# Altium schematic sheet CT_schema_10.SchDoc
size 741 x 377 mm
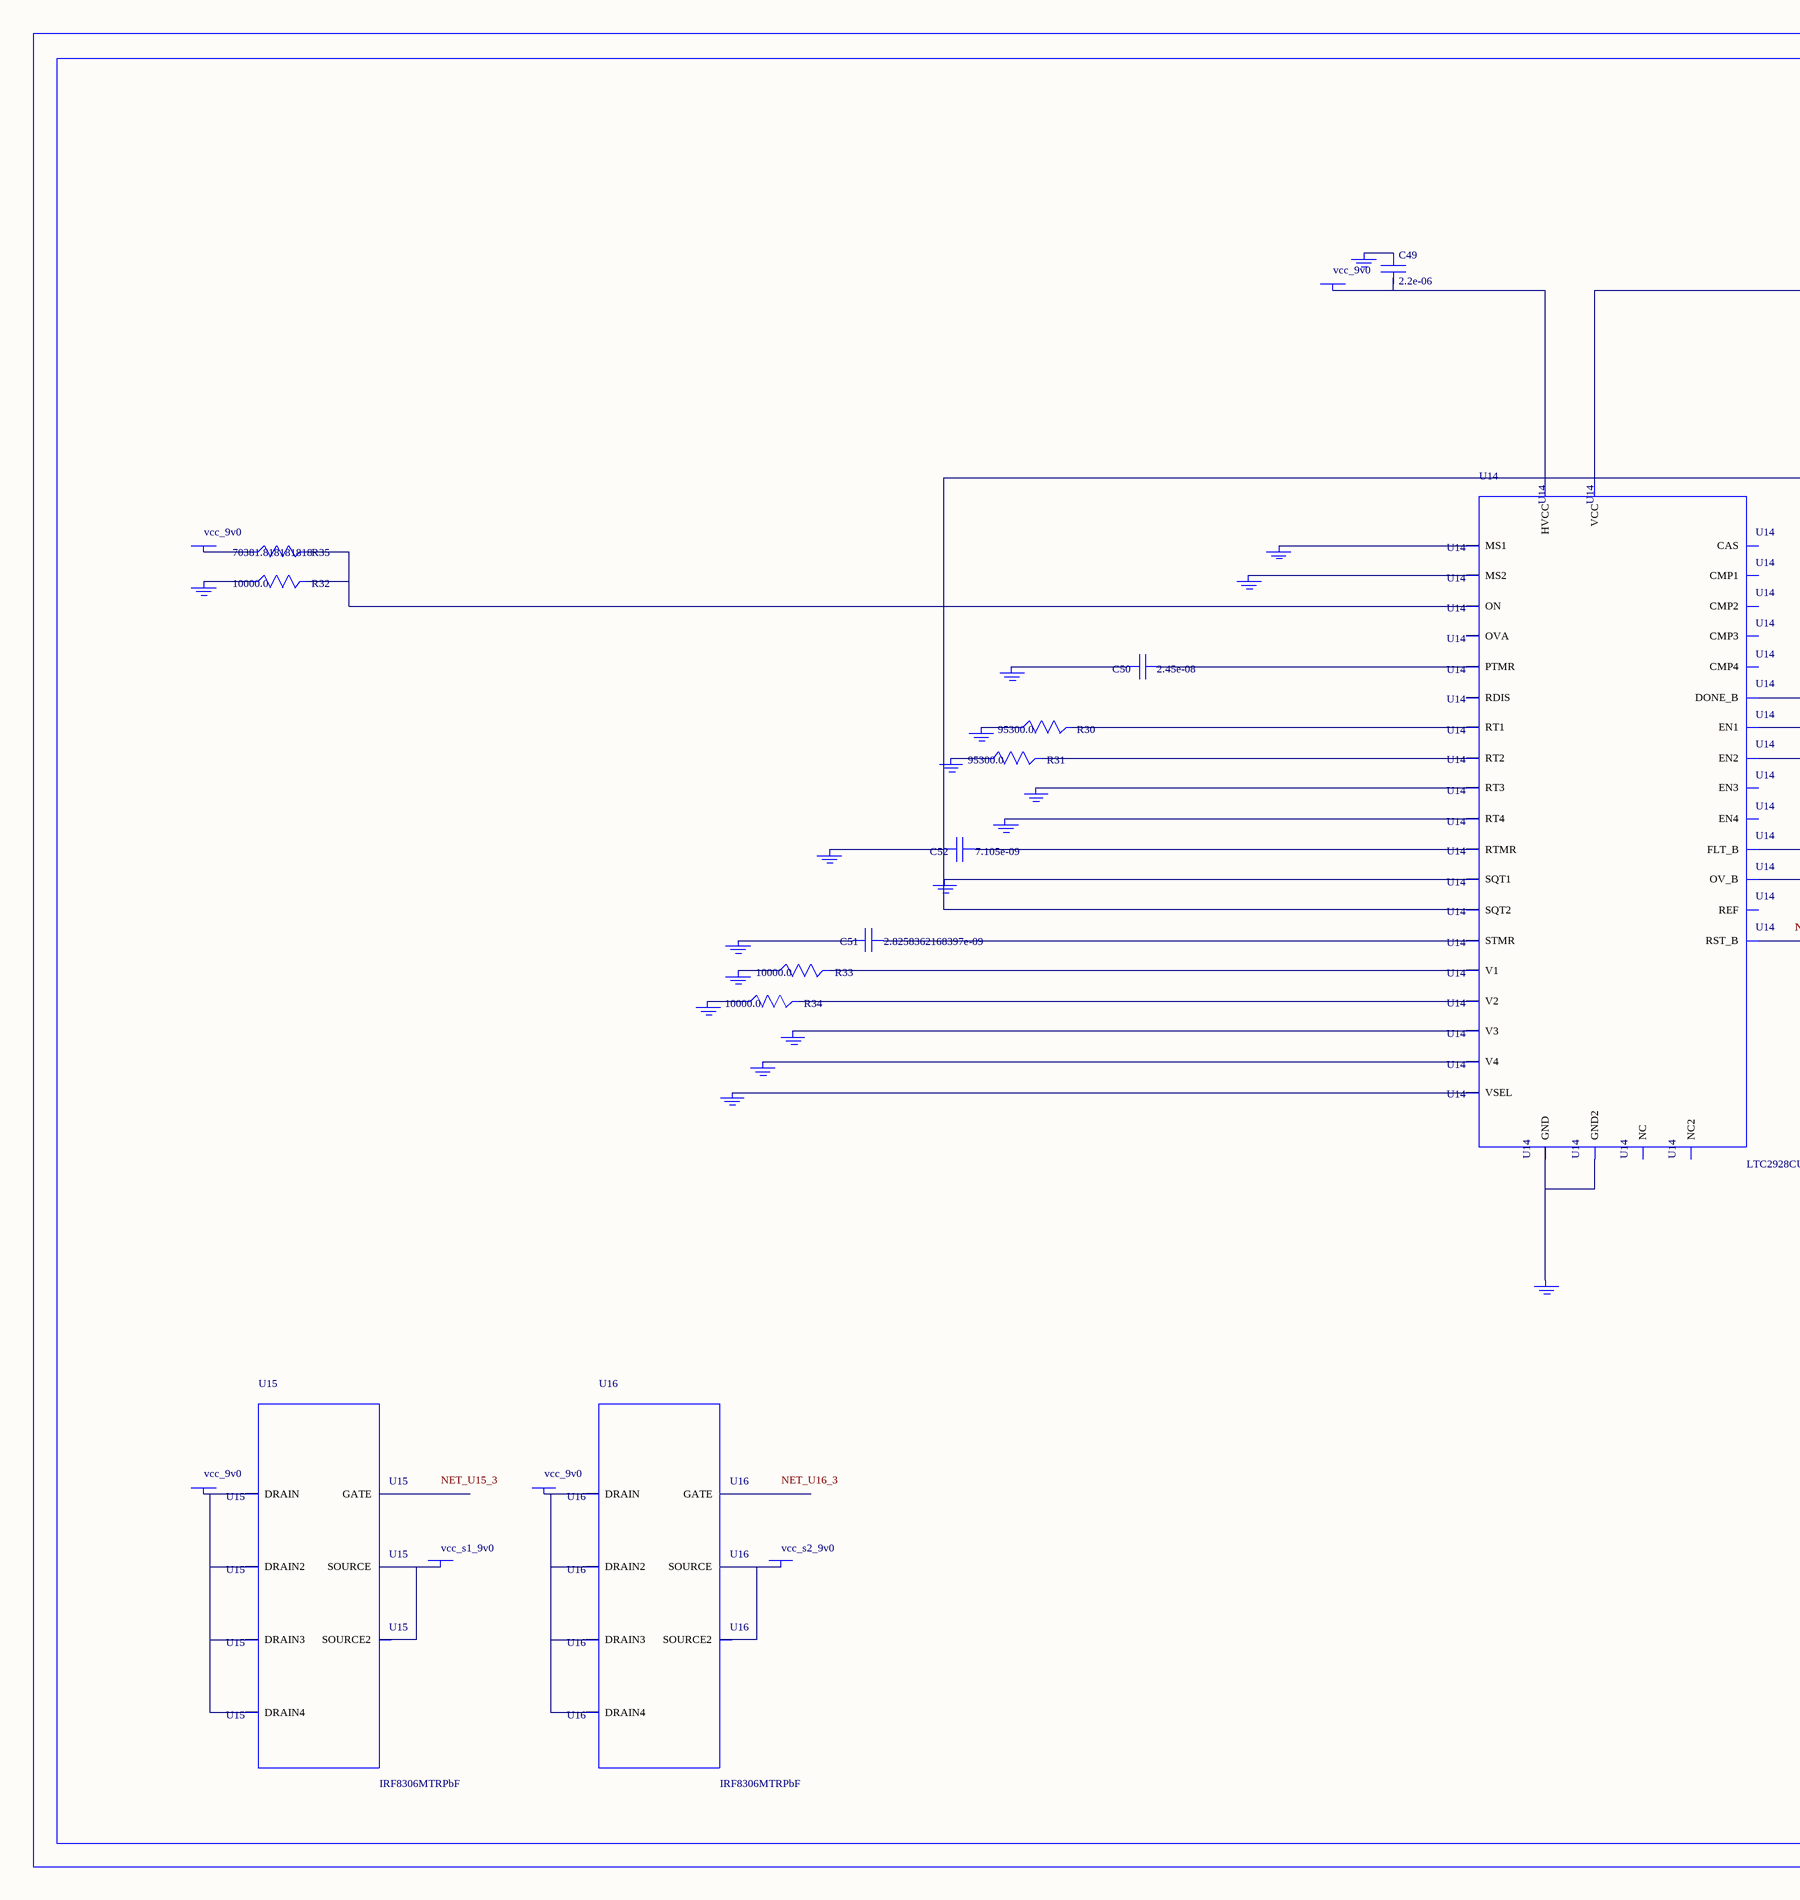
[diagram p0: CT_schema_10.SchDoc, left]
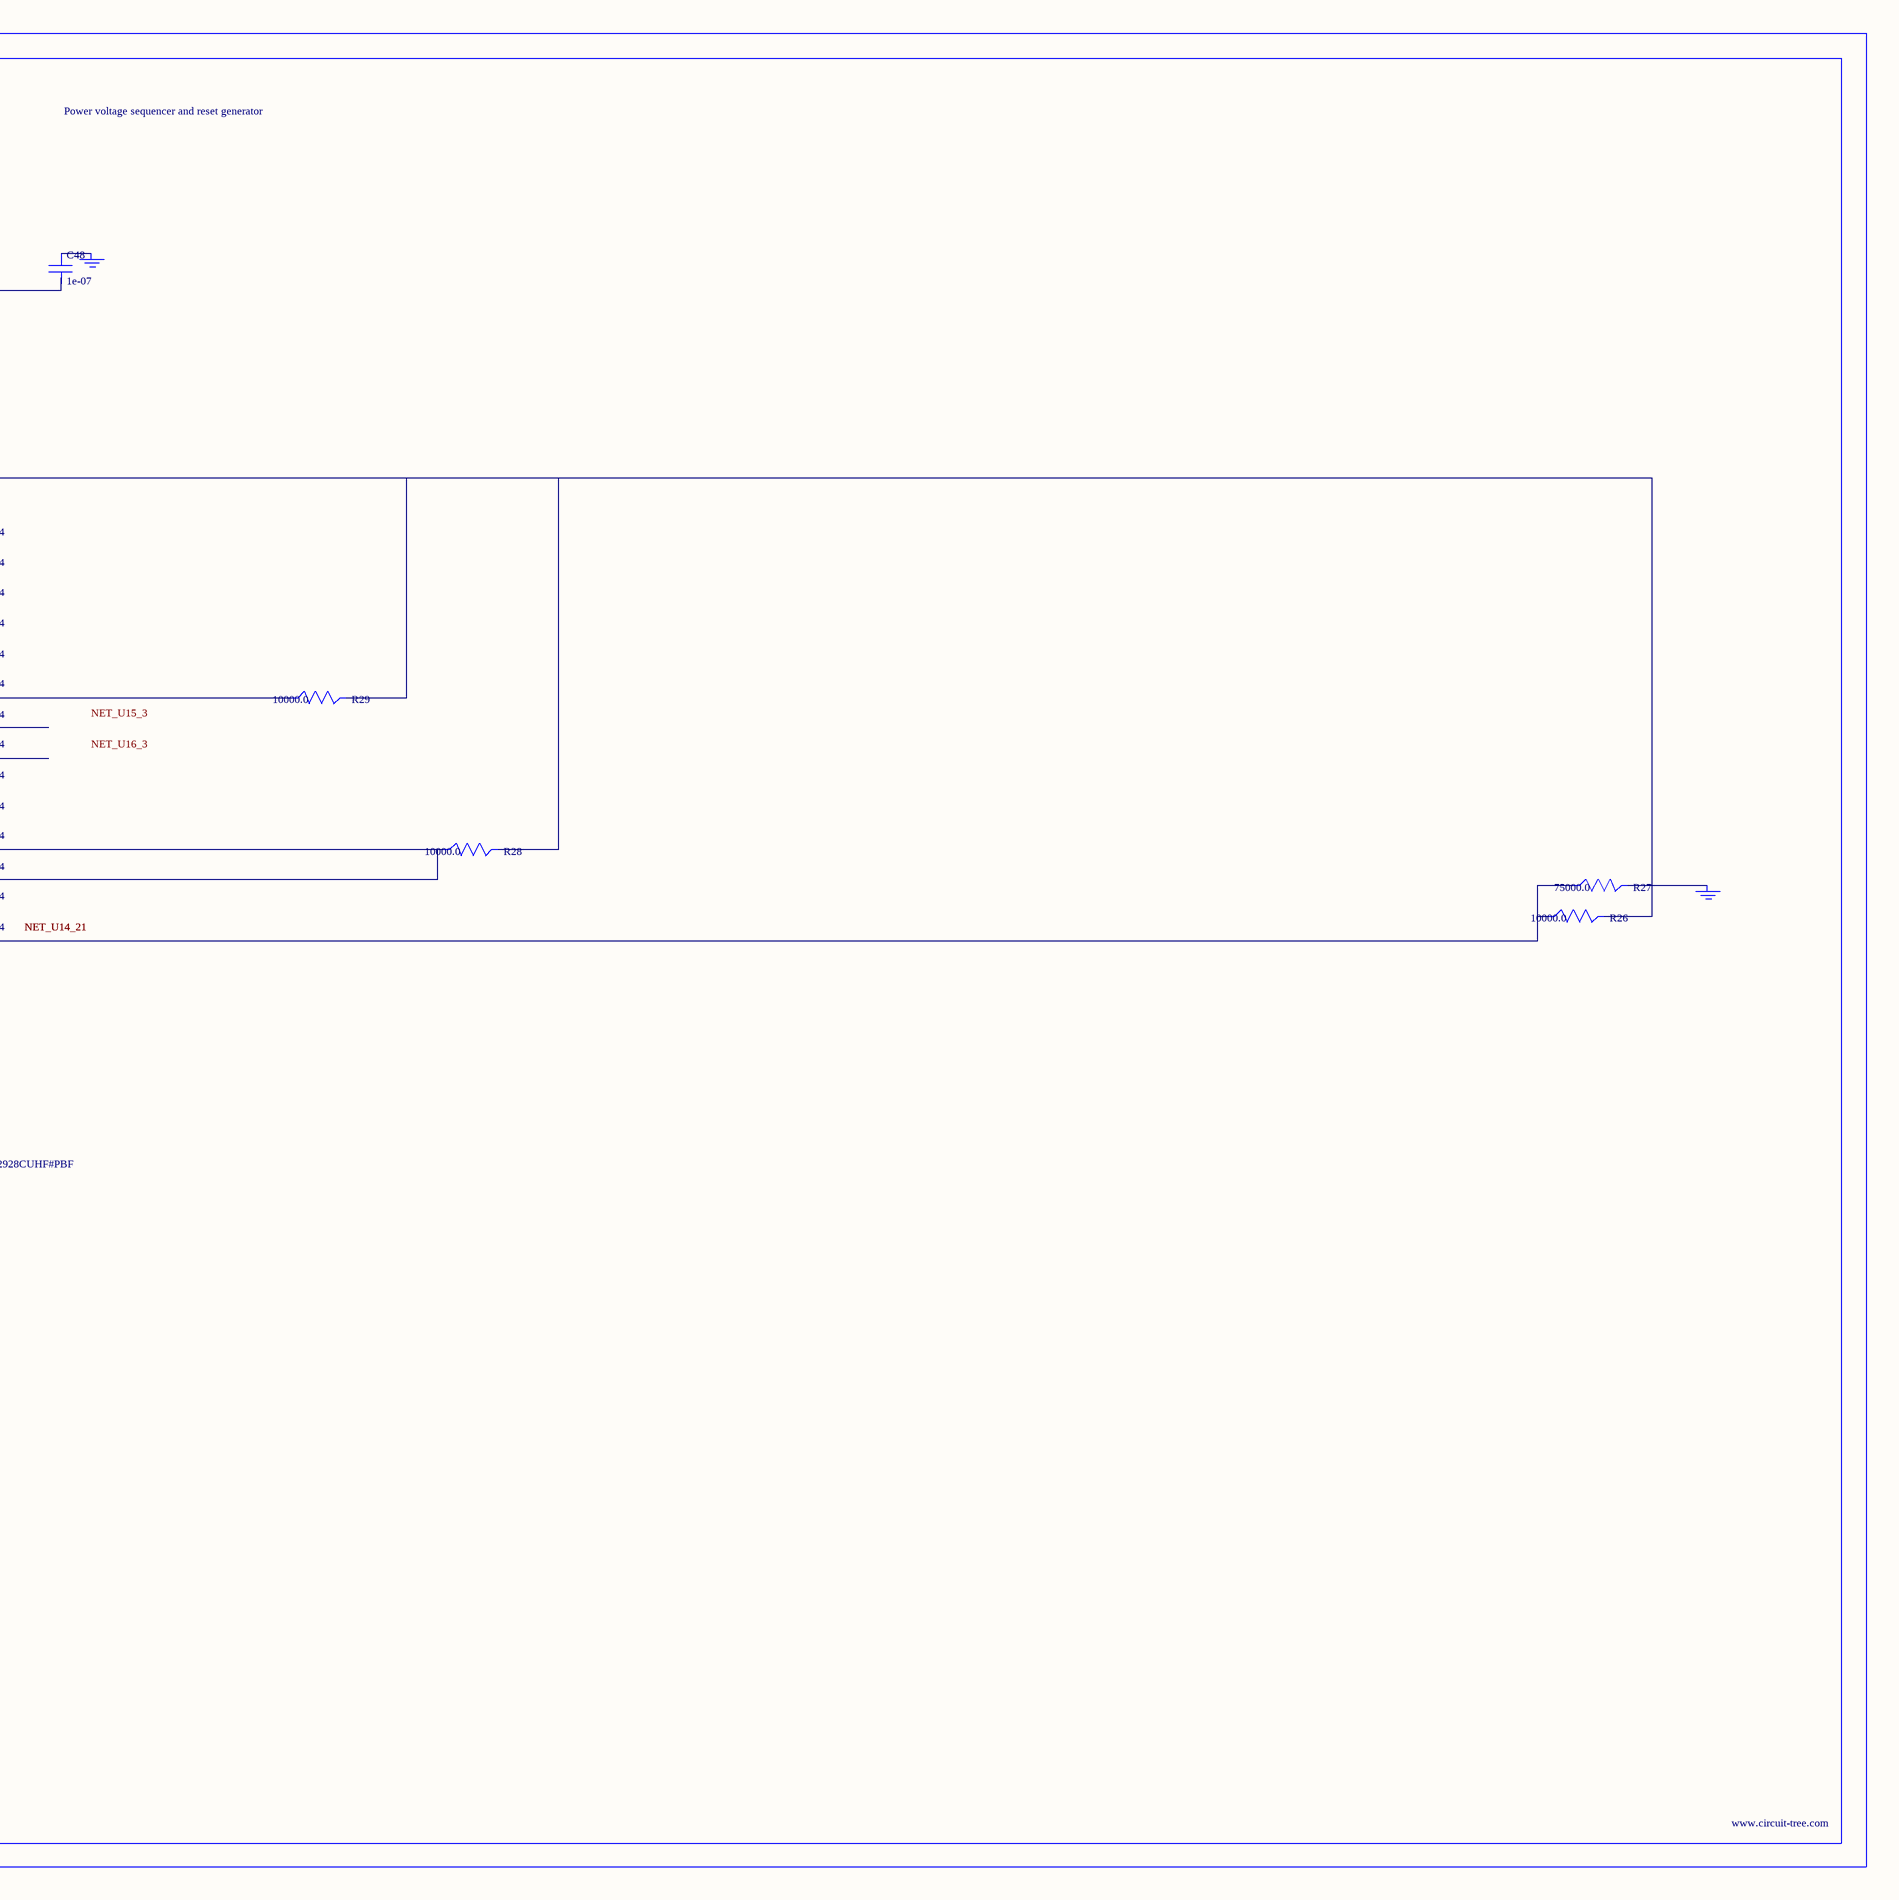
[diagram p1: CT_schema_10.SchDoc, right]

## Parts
BORDER9  (no value)
C48  1e-07  [C0402]
C49  2.2e-06  [C0603]
C50  2.45e-08  [R0603]
C51  2.8258362168397e-09  [R0603]
C52  7.105e-09  [R0603]
GND_INSTANCE_9_0  (no value)
GND_INSTANCE_9_1  (no value)
GND_INSTANCE_9_2  (no value)
GND_INSTANCE_9_3  (no value)
GND_INSTANCE_9_4  (no value)
GND_INSTANCE_9_5  (no value)
GND_INSTANCE_9_6  (no value)
GND_INSTANCE_9_7  (no value)
GND_INSTANCE_9_8  (no value)
GND_INSTANCE_9_9  (no value)
GND_INSTANCE_9_10  (no value)
GND_INSTANCE_9_11  (no value)
GND_INSTANCE_9_12  (no value)
GND_INSTANCE_9_13  (no value)
GND_INSTANCE_9_14  (no value)
GND_INSTANCE_9_15  (no value)
GND_INSTANCE_9_16  (no value)
GND_INSTANCE_9_17  (no value)
GND_INSTANCE_9_18  (no value)
GND_INSTANCE_9_19  (no value)
POWER_INSTANCE_9_0  vcc_9v0
POWER_INSTANCE_9_1  vcc_9v0
POWER_INSTANCE_9_2  vcc_9v0
POWER_INSTANCE_9_3  vcc_s1_9v0
POWER_INSTANCE_9_4  vcc_9v0
POWER_INSTANCE_9_5  vcc_s2_9v0
R26  10000.0  [R0603]
R27  75000.0  [R0603]
R28  10000.0  [R0603]
R29  10000.0  [R0603]
R30  95300.0  [R0603]
R31  95300.0  [R0603]
R32  10000.0  [R0603]
R33  10000.0  [R0603]
R34  10000.0  [R0603]
R35  70381.818181818  [R0603]
U14  LTC2928CUHF#PBF  [QFN-38_UHF]
U15  IRF8306MTRPbF  [IRF8306MTRPBF]
U16  IRF8306MTRPbF  [IRF8306MTRPBF]

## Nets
NetC48_1: C48.1 GND_INSTANCE_9_10.0(GND)
NetC48_2: C48.2 C52.2 GND_INSTANCE_9_5.0(GND) GND_INSTANCE_9_15.0(GND) R26.2 R28.2 R29.2 U14.10(SQT1) U14.11(SQT2) U14.22(VCC)
NetC49_1: C49.1 GND_INSTANCE_9_11.0(GND)
NetC49_2: C49.2 POWER_INSTANCE_9_1.0(PWR) U14.23(HVCC)
NetC50_1: C50.1 U14.27(PTMR)
NetC50_2: C50.2 GND_INSTANCE_9_14.0(GND)
NetC51_1: C51.1 U14.26(STMR)
NetC51_2: C51.2 GND_INSTANCE_9_13.0(GND)
NetC52_1: C52.1 U14.28(RTMR)
NetGND_INSTANCE_9_0_0: GND_INSTANCE_9_0.0(GND) R33.1
NetGND_INSTANCE_9_1_0: GND_INSTANCE_9_1.0(GND) R30.1
NetGND_INSTANCE_9_2_0: GND_INSTANCE_9_2.0(GND) R31.1
NetGND_INSTANCE_9_3_0: GND_INSTANCE_9_3.0(GND) U14.8(RT3)
NetGND_INSTANCE_9_4_0: GND_INSTANCE_9_4.0(GND) U14.9(RT4)
NetGND_INSTANCE_9_6_0: GND_INSTANCE_9_6.0(GND) U14.12(MS1)
NetGND_INSTANCE_9_7_0: GND_INSTANCE_9_7.0(GND) U14.13(MS2)
NetGND_INSTANCE_9_8_0: GND_INSTANCE_9_8.0(GND) R32.1
NetGND_INSTANCE_9_9_0: GND_INSTANCE_9_9.0(GND) R27.2
NetGND_INSTANCE_9_12_0: GND_INSTANCE_9_12.0(GND) U14.25(VSEL)
NetGND_INSTANCE_9_16_0: GND_INSTANCE_9_16.0(GND) U14.30(V4)
NetGND_INSTANCE_9_17_0: GND_INSTANCE_9_17.0(GND) U14.32(V3)
NetGND_INSTANCE_9_18_0: GND_INSTANCE_9_18.0(GND) R34.1
NetGND_INSTANCE_9_19_0: GND_INSTANCE_9_19.0(GND) U14.24(GND) U14.39(GND2)
NetPOWER_INSTANCE_9_0_0: POWER_INSTANCE_9_0.0(PWR) R35.1
NetPOWER_INSTANCE_9_2_0: POWER_INSTANCE_9_2.0(PWR) U15.1(DRAIN) U15.2(DRAIN2) U15.6(DRAIN3) U15.7(DRAIN4)
NetPOWER_INSTANCE_9_3_0: POWER_INSTANCE_9_3.0(PWR) U15.4(SOURCE) U15.5(SOURCE2)
NetPOWER_INSTANCE_9_4_0: POWER_INSTANCE_9_4.0(PWR) U16.1(DRAIN) U16.2(DRAIN2) U16.6(DRAIN3) U16.7(DRAIN4)
NetPOWER_INSTANCE_9_5_0: POWER_INSTANCE_9_5.0(PWR) U16.4(SOURCE) U16.5(SOURCE2)
NetR26_1: R26.1 R27.1 U14.21(RST_B)
NetR28_1: R28.1 U14.19(FLT_B) U14.20(OV_B)
NetR29_1: R29.1 U14.18(DONE_B)
NetR30_2: R30.2 U14.6(RT1)
NetR31_2: R31.2 U14.7(RT2)
NetR32_2: R32.2 R35.2 U14.16(ON)
NetR33_2: R33.2 U14.3(V1)
NetR34_2: R34.2 U14.38(V2)

Not connected (* = marked no-connect by the designer): U14 1(OVA) 2(EN1) 4(NC) 5(REF) 14(RDIS) 15(CAS) 17(NC2) 29(EN4) 31(EN3) 33(CMP3) 34(CMP4) 35(CMP1) 36(CMP2) 37(EN2); U15 3(GATE); U16 3(GATE)

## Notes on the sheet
- Labels drawn without touching a wire or pin: NET_U15_3, NET_U16_3

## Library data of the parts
BORDER9 = BORDER_PAGE9
C48 = C0402C104K3RACTU
C49 = GRM188R61H225KE1115D
C50 = C50
C51 = C51
C52 = C52
GND_INSTANCE_9_0-GND_INSTANCE_9_19 = GND
POWER_INSTANCE_9_0-POWER_INSTANCE_9_5 = PWR
R26 R28 R29 R32-R34 = RC0603JR-0710KL
R27 = RC0603JR-0775KL
R30 R31 = RC0603FR-0795K3L
R35 = R35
